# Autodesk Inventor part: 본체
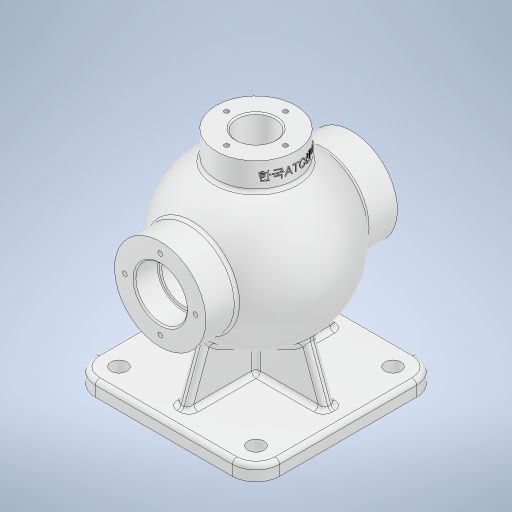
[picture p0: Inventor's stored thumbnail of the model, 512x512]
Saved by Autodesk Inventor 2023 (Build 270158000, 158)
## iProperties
Created: 2023-07
Part Number: 본체
Material: 알루미늄 6061
Document SubType Name: Modeling
Designer: Owner
Density: 2.7 g/cm^3
Appearance: 알루미늄 - 평지
Mass: 1526.72 g
Surface Area: 1173.82 cm^2
Volume: 565.453 cm^3
Author: Owner
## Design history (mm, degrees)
sketch "스케치1"
  geometry: L1 (62.5, 62.5)-(-62.5, 62.5); L2 (-62.5, 62.5)-(-62.5, -62.5); L3 (-62.5, -62.5)-(62.5, -62.5); L4 (62.5, -62.5)-(62.5, 62.5); L5 (62.5, 62.5)-(-62.5, -62.5); L6 (-62.5, 62.5)-(62.5, -62.5); 1 further point
  constraints: 12 end point, 2 midpoint, 2 parallel, 1 horizontal, 1 perpendicular
  dimensions: "d0" = 125 distance of L3.end L2.end; "d1" = 125 distance of L2.end L1.end
extrude "돌출1" new body sketch "스케치1" distance "d2" = 10; taper "d3" = 0 deg
sketch "스케치2"
  geometry: L1 (85, 65)-(85, -65); L2 (0, -62.5)-(0, 62.5) reference; L3 (85, 65)-(54, 65); L4 (54, -65)-(85, -65); L5 (54, 65)-(54, 44.215); L6 (54, -44.215)-(54, -65); A1 r 54 centre (85, 0) between (54, 44.215) and (54, -44.215); 8 further points
  constraints: 10 end point, 4 horizontal alignment, 3 vertical, 2 horizontal, 2 midpoint, 2 point on circle, 1 centre point, 1 coincident, 1 collinear, 6 other
  dimensions: "d5" = 85 distance between parallel lines of L2 L1; "d8" = 130 distance between parallel lines of L4 L3; "d11" = 31 distance of L1.start L3.end; "d12" = 54 radius of A1
revolve "회전1" sketch "스케치2" stored, may be unused: angle "d13" = 90 deg
sketch "스케치3"
  geometry: L1 (10, 50.5)-(85, 23.202); L2 (85, 23.202)-(85, -23.202); L3 (85, -23.202)-(10, -50.5); L4 (10, -62.5)-(10, 62.5) reference; L5 (0, -62.5)-(0, 62.5) reference; L6 (0, -62.5)-(10, -62.5) reference; L7 (0, 62.5)-(10, 62.5) reference; 1 further point
  constraints: 6 end point, 2 point on line, 1 vertical
  dimensions: "d14" = 12 distance from line of L6 L3.end; "d15" = 20 deg angle of L6 L3; "d16" = 12 distance from line of L7 L1.start; "d17" = 20 deg angle of L7 L1; "d18" = 85 distance between parallel lines of L5 L2
extrude "돌출2" join sketch "스케치3" stored distance "d19" = 8; taper "d20" = 0 deg
sketch "스케치4"
  geometry: L1 (62.5, 10)-(-62.5, 10) reference; L2 (62.5, 0)-(62.5, 10) reference; L3 (-62.5, 0)-(-62.5, 10) reference; L4 (-39.65, 39.811)-(-50.5, 10); L5 (-62.5, 10)-(62.5, 10) reference; A1 r 54 centre (0, 85) between (4, 31.148) and (-4, 31.148) reference; 1 further point
  constraints: 2 end point, 1 point on line
  dimensions: "d25" = 12 distance from line of L3 L4.end; "d26" = 20 deg angle of L3 L4
feature "리브1" sketch "스케치4" dims "d27" = 1, "d28" = 8, "d29" = 0, "d30" = 0, "d31" = 1, "d32" = 1
sketch "스케치5"
  geometry: L1 (54, 65)-(116, 65) reference; L2 (85, 65)-(85, -65); L3 (54, -65)-(116, -65) reference; A1 r 44 centre (85, 0) between (85, -44) and (85, 44); 1 further point
  constraints: 3 midpoint, 2 end point, 2 point on circle, 2 point on line, 1 centre point
  dimensions: "d33" = 88 diameter of A1
revolve "회전2" sketch "스케치5" stored, may be unused: angle "d34" = 90 deg
sketch "스케치6"
  geometry: C1 r 31 at (0, 0) reference; C2 r 17.5 at (0, 0); 1 further point
  constraints: 1 centre point, 1 coincident
  dimensions: "d35" = 35 diameter of C2
extrude "돌출3" cut sketch "스케치6" distance "d36" = 16; taper "d37" = 0 deg
sketch "스케치7"
  geometry: C1 r 17.5 at (0, 0) reference; C2 r 15 at (0, 0); 1 further point
  constraints: 1 centre point, 1 coincident
  dimensions: "d38" = 30 diameter of C2
extrude "돌출4" cut sketch "스케치7" stored distance "d39" = 10; taper "d40" = 0 deg
node "작업 평면1"
sketch "스케치8"
  geometry: C1 r 27 at (0, 0); 1 further point
  constraints: 1 centre point, 1 coincident
  dimensions: "d42" = 54 diameter of C1
extrude "돌출5" join sketch "스케치8" stored distance "d43" = 10; taper "d44" = 0 deg
sketch "스케치9"
  geometry: C1 r 27 at (0, 0) reference; C2 r 13 at (0, 0)
  constraints: 1 centre point, 1 coincident
  dimensions: "d45" = 26 diameter of C2
extrude "돌출6" cut sketch "스케치9" stored distance "d46" = 10; taper "d47" = 0 deg
sketch "스케치10"
  geometry: L1 (-62.5, -85)-(62.5, -85) reference; C1 r 17.5 at (0, 0) reference; 2 further points
  dimensions: "d48" = 85 distance from line of L1 point (-24, 0); "d49" = 24 distance of C1.centre point (-24, 0)
hole "구멍1" sketch "스케치10" at (-24, 0) diameter "d50" = 3.242; stored, may be unused: countersink angle "d54" = 90 deg, drill point angle "d56" = 118 deg; dims "d51" = 12, "d52" = 4, "d53" = 2, "d55" = 15
sketch "스케치11"
  geometry: C1 r 13 at (0, 0) reference; 1 further point
  constraints: 1 vertical alignment
  dimensions: "d60" = 20 distance of C1.centre point (0, -20)
hole "구멍2" sketch "스케치11" at (0, -20) diameter "d61" = 3.242; stored, may be unused: countersink angle "d65" = 90 deg, drill point angle "d67" = 118 deg; dims "d62" = 9, "d63" = 4, "d64" = 2, "d66" = 11
fillet "모깎기1" dims "d71" = 3
fillet "모깎기2" dims "d72" = 3
fillet "모깎기3" dims "d73" = 3
fillet "모깎기4" dims "d74" = 3
chamfer "모따기1" distance "d75" = 1; stored, may be unused: second distance "d76" = 2, angle "d77" = 45 deg
fillet "모깎기5" dims "d78" = 16
fillet "모깎기6" dims "d79" = 3
sketch "스케치12"
  geometry: C1 r 5.5 at (-46.5, 46.5); A1 r 13 centre (-46.5, 46.5) between (-46.5, 59.5) and (-59.5, 46.5) reference; 1 further point
  constraints: 1 centre point, 1 coincident
  dimensions: "d80" = 11 diameter of C1
extrude "돌출7" cut sketch "스케치12" extent not by distance; stored distance "d81" = 0; taper "d82" = 0 deg
node "작업 평면2"
sketch "스케치13"
  geometry: L1 (0, -27)-(0, 27) reference; L2 (-150, 46.5)-(-150, -46.5) reference; 3 further points
  constraints: 1 horizontal alignment, 1 midpoint, 1 other
  dimensions: "d83" = 9 distance from line of L1 point (-9, 0)
feature "엠보싱1" sketch "스케치13" dims "d84" = 0.5, "d85" = 0
fillet "모깎기7" dims "d86" = 0.6
node "솔리드1"
mirror "미러1"
mirror "미러2"
pattern_circular "원형 패턴1" dims angle "d58" = 360 deg
mirror "미러3"
pattern_circular "원형 패턴2" dims angle "d69" = 360 deg
mirror "미러4"
mirror "미러5"
feature "A9D066F2-1C7D-4E18-AEED-F7BC21143FA4" dims "d50" = 3.242, "d51" = 12, "d52" = 4, "d53" = 2, "d54" = 90 deg, "d55" = 15, "d56" = 118 deg
